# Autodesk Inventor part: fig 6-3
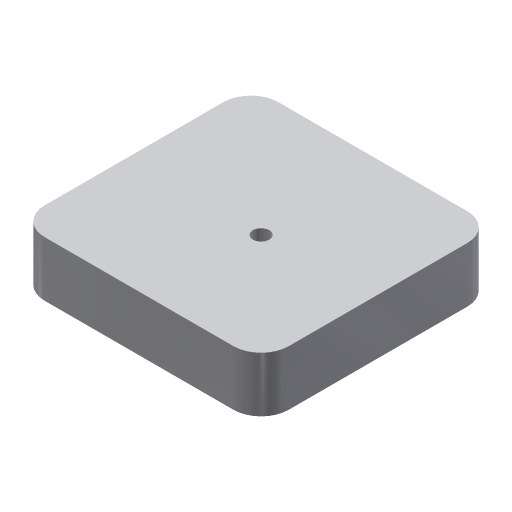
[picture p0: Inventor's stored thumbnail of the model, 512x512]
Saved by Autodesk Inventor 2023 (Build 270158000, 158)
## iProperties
Created: 2004-05
Part Number: fig 6-3
Document SubType Name: Modeling
Designer: CADCIM Technologies
Manufacturer: Standard
Standards Organization: Custom
Density: 1 g/cm^3
Material: Generic
Appearance: Default
Author: CADCIM Technologies
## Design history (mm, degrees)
sketch "Sketch1"
  geometry: L1 (0, 0)-(44.293, 0); L2 (44.293, 0)-(44.293, 42.442); L3 (44.293, 42.442)-(0, 42.442); L4 (0, 42.442)-(0, 0)
  constraints: 8 end point, 2 parallel, 1 horizontal, 1 perpendicular
extrude "Extrusion1" new body sketch "Sketch1" distance "d0" = 10; taper "d1" = 0 deg
fillet "Fillet1" dims "d2" = 5
hole "Hole1" diameter "d6" = 3; stored, may be unused: countersink angle "d10" = 90 deg, drill point angle "d12" = 118 deg; dims "d4" = 20, "d5" = 20, "d7" = 6, "d8" = 4, "d9" = 2, "d11" = 8
body "Solid1"
